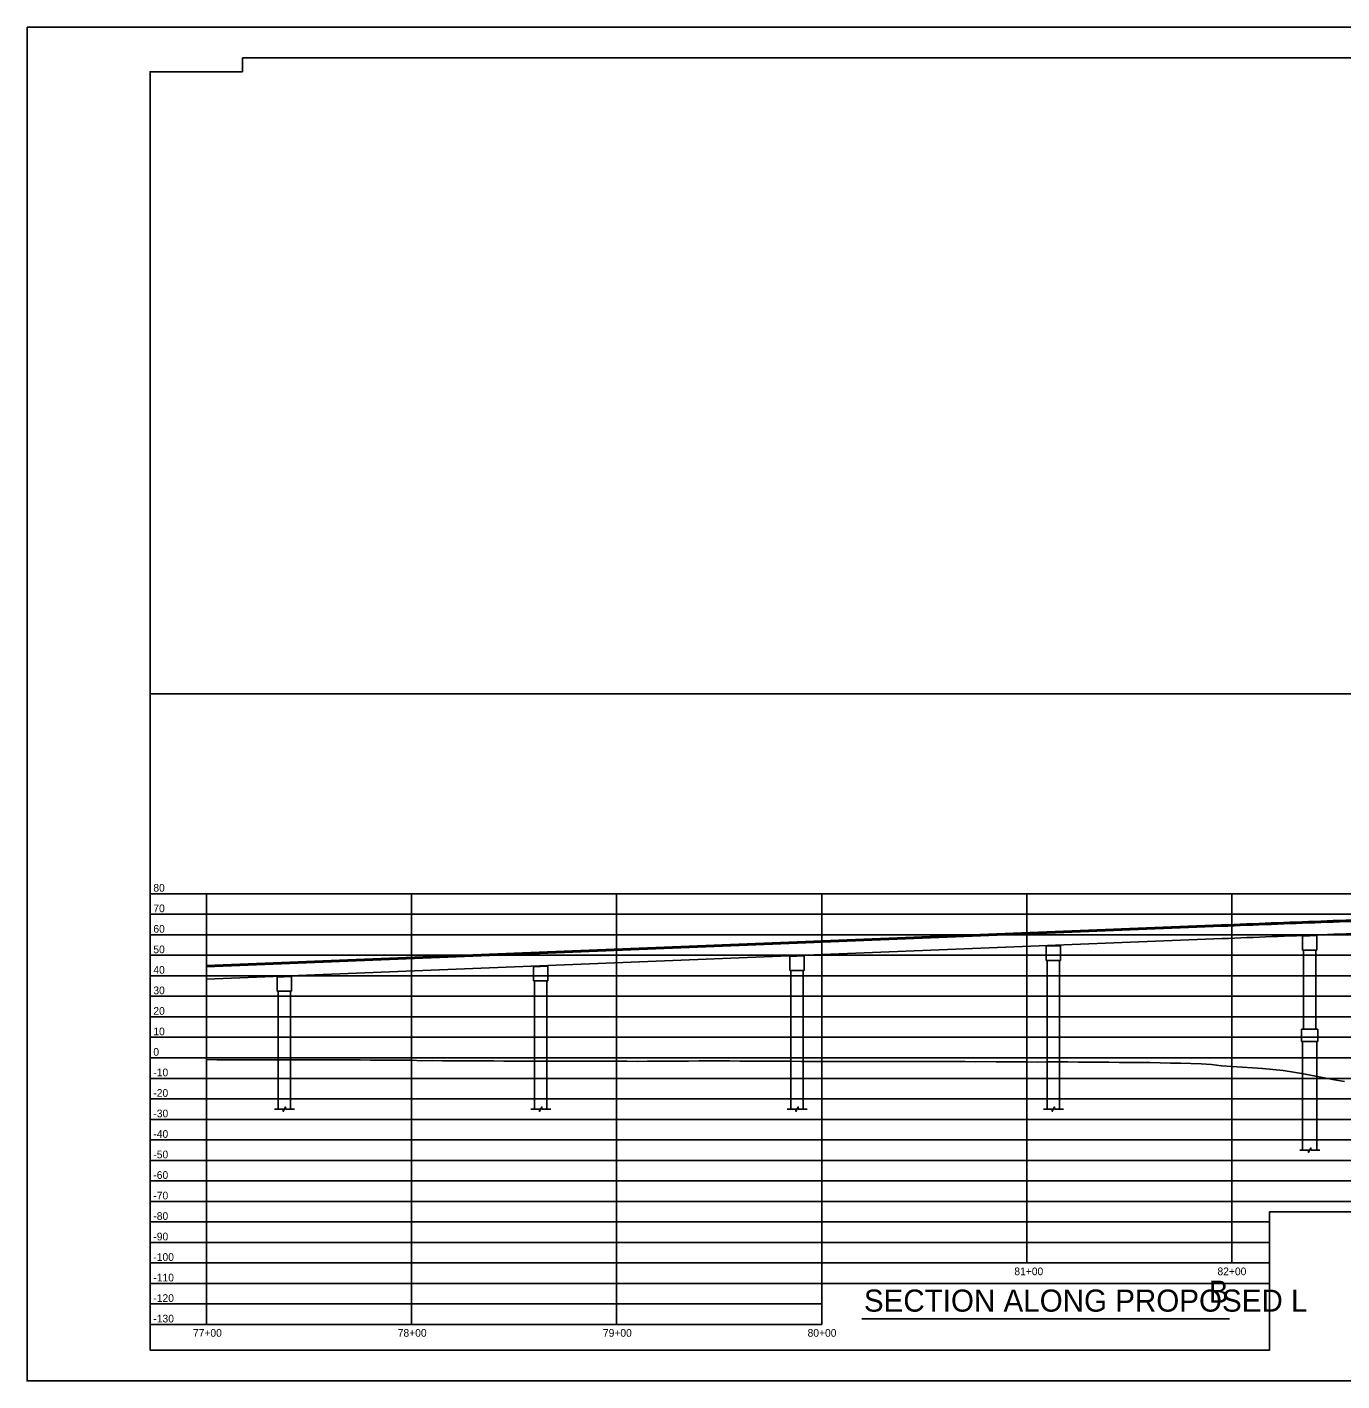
# Model space of a CAD drawing. Extents: x -464 to 4306, y -1372 to 300.
# Drawn here: x 766 to 1407, y -1372 to -712 of the extents above; entities that cross this region are included whole.
import ezdxf

# ---------------------------------------------------------------- set-up
doc = ezdxf.new("R2010")
doc.units = 0
for name, color, linetype in [('BR_AUTO DIMENSION', 7, 'Continuous'), ('BR_BORDER LINES', 7, 'Continuous'), ('BR_GRID LINES', 7, 'Continuous'), ('BR_TEXT', 7, 'Continuous'), ('Mis Ground Lines', 7, 'Continuous'), ('NOPLOT', 7, 'Continuous'), ('Sheet Plot Border Outside CELL', 7, 'Continuous'), ('sub interior bent cap lines', 7, 'Continuous'), ('Sup Concrete Girder Lines', 7, 'Continuous'), ('Sup Concrete Slab Lines', 7, 'Continuous')]:
    doc.layers.add(name, color=color, linetype=linetype)

msp = doc.modelspace()

# ---------------------------------------------------------------- linework, layer by layer
at = {"layer": 'BR_AUTO DIMENSION'}
msp.add_line((853.5, -1164.94), (853.5, -1224.94), dxfattribs=at)
for points in [[(886.62, -1239.94), (890.94, -1239.94), (890.94, -1241.06), (892.06, -1238.83), (892.06, -1239.94), (896.37, -1239.94)], [(1011.62, -1239.94), (1015.94, -1239.94), (1015.94, -1241.06), (1017.06, -1238.83), (1017.06, -1239.94), (1021.37, -1239.94)], [(1136.62, -1239.94), (1140.94, -1239.94), (1140.94, -1241.06), (1142.06, -1238.83), (1142.06, -1239.94), (1146.37, -1239.94)], [(1261.62, -1239.94), (1265.94, -1239.94), (1265.94, -1241.06), (1267.06, -1238.83), (1267.06, -1239.94), (1271.37, -1239.94)], [(1386.62, -1259.94), (1390.94, -1259.94), (1390.94, -1261.06), (1392.06, -1258.83), (1392.06, -1259.94), (1396.37, -1259.94)]]:
    msp.add_lwpolyline(points, dxfattribs=at)
at = {"layer": 'BR_BORDER LINES'}
msp.add_line((826, -1037.44), (1831, -1037.44), dxfattribs=at)
at = {"layer": 'BR_GRID LINES'}
for p, q in [((826, -1134.94), (1831, -1134.94)), ((853.5, -1344.94), (853.5, -1134.94)), ((953.5, -1344.94), (953.5, -1134.94)), ((1053.5, -1344.94), (1053.5, -1134.94)), ((1153.5, -1344.94), (1153.5, -1134.94)), ((1253.5, -1314.94), (1253.5, -1134.94)), ((1353.5, -1314.94), (1353.5, -1134.94)), ((826, -1144.94), (1831, -1144.94)), ((826, -1154.94), (1831, -1154.94)), ((826, -1164.94), (1831, -1164.94)), ((826, -1174.94), (1831, -1174.94)), ((826, -1184.94), (1831, -1184.94)), ((826, -1194.94), (1831, -1194.94)), ((826, -1204.94), (1831, -1204.94)), ((826, -1214.94), (1831, -1214.94)), ((826, -1224.94), (1831, -1224.94)), ((826, -1234.94), (1831, -1234.94)), ((826, -1244.94), (1831, -1244.94)), ((826, -1254.94), (1831, -1254.94)), ((826, -1264.94), (1831, -1264.94)), ((826, -1274.94), (1606, -1274.94)), ((826, -1284.94), (1606, -1284.94)), ((826, -1294.94), (1371.93, -1294.94)), ((826, -1304.94), (1371.93, -1304.94)), ((826, -1314.94), (1371.93, -1314.94)), ((826, -1324.94), (1371.93, -1324.94)), ((826, -1334.94), (1153.5, -1334.94)), ((826, -1344.94), (1153.5, -1344.94))]:
    msp.add_line(p, q, dxfattribs=at)
at = {"layer": 'BR_TEXT'}
msp.add_line((1173.09, -1342.1), (1352.35, -1342.1), dxfattribs=at)
at = {"layer": 'Mis Ground Lines'}
for points in [[(853.5, -1215.83), (858.5, -1215.84), (863.5, -1215.85), (868.5, -1215.86), (873.5, -1215.87), (878.5, -1215.88), (883.5, -1215.89), (888.5, -1215.9), (893.5, -1215.91), (898.5, -1215.92), (903.5, -1215.93), (908.5, -1215.94), (913.5, -1215.95), (918.5, -1215.96), (923.5, -1215.97), (928.5, -1215.98), (933.5, -1216.01), (938.5, -1216.04), (943.5, -1216.07), (948.5, -1216.1), (953.5, -1216.13), (958.5, -1216.34), (963.5, -1216.2), (968.5, -1216.4), (973.5, -1216.41), (978.5, -1216.37), (983.5, -1216.36), (988.5, -1216.42), (993.5, -1216.43), (998.5, -1216.52), (1003.5, -1216.5), (1008.5, -1216.53), (1013.5, -1216.6), (1018.5, -1216.63), (1023.5, -1216.56), (1028.5, -1216.53), (1033.5, -1216.62), (1038.5, -1216.6), (1043.5, -1216.61), (1048.5, -1216.62), (1053.5, -1216.6), (1058.5, -1216.64), (1063.5, -1216.67), (1068.5, -1216.61), (1073.5, -1216.62), (1078.5, -1216.56), (1083.5, -1216.53), (1088.5, -1216.55), (1093.5, -1216.45), (1098.5, -1216.47), (1103.5, -1216.48), (1108.5, -1216.48), (1113.5, -1216.5), (1118.5, -1216.53), (1123.5, -1216.6), (1128.5, -1216.58), (1133.5, -1216.61), (1138.5, -1216.59), (1143.5, -1216.65), (1148.5, -1216.65), (1153.5, -1216.7)], [(1153.5, -1216.7), (1158.5, -1216.75), (1163.5, -1216.71), (1168.5, -1216.77), (1173.5, -1216.7), (1178.5, -1216.74), (1183.5, -1216.75), (1188.5, -1216.67), (1193.5, -1216.75), (1198.5, -1216.7), (1203.5, -1216.78), (1208.5, -1216.8), (1213.5, -1216.8), (1218.5, -1216.8), (1223.5, -1216.78), (1228.5, -1216.81), (1233.5, -1216.77), (1238.5, -1216.84), (1243.5, -1216.85), (1248.5, -1216.85), (1253.5, -1216.96), (1258.5, -1216.99), (1263.5, -1216.91), (1268.5, -1216.92), (1273.5, -1216.86), (1278.5, -1216.98), (1283.5, -1216.99), (1288.5, -1217.02), (1293.5, -1217.11), (1298.5, -1217.14), (1303.5, -1217.25), (1308.5, -1217.14), (1313.5, -1217.24), (1318.5, -1217.33), (1323.5, -1217.48), (1328.5, -1217.58), (1333.5, -1217.76), (1338.5, -1217.94), (1343.5, -1218.14), (1348.5, -1218.79), (1353.5, -1219.12), (1358.5, -1219.48), (1363.5, -1219.83), (1368.5, -1220.21), (1373.5, -1220.56), (1378.5, -1221.19), (1383.5, -1221.99), (1388.5, -1222.79), (1393.5, -1223.68), (1398.5, -1224.64), (1403.5, -1225.59), (1408.5, -1226.47)]]:
    msp.add_lwpolyline(points, dxfattribs=at)
at = {"layer": 'NOPLOT'}
msp.add_lwpolyline([(871, -727.45), (871, -734.19), (826, -734.19), (826, -1357.44), (1371.93, -1357.44), (1371.93, -1289.94), (1606, -1289.94), (1606, -1274.94), (1831, -1274.94), (1831, -747.45), (1756, -747.45), (1756, -727.45)], close=True, dxfattribs=at)
at = {"layer": 'Sheet Plot Border Outside CELL'}
msp.add_lwpolyline([(766, -712.44), (1846, -712.44), (1846, -1372.44), (766, -1372.44)], close=True, dxfattribs=at)
at = {"layer": 'sub interior bent cap lines'}
for p, q in [((1270, -1160.29), (1263, -1160.57)), ((1263, -1160.57), (1263, -1167.43)), ((1270, -1160.29), (1270, -1167.43)), ((1395, -1155.36), (1388, -1155.62)), ((1388, -1155.62), (1388, -1162.49)), ((1395, -1155.36), (1395, -1162.49)), ((1145, -1165.29), (1138, -1165.57)), ((1138, -1165.57), (1138, -1172.43)), ((1145, -1165.29), (1145, -1172.43)), ((1263, -1167.43), (1270, -1167.43)), ((1263.5, -1167.43), (1263.5, -1239.94)), ((1269.5, -1167.43), (1269.5, -1239.94)), ((1388, -1162.49), (1395, -1162.49)), ((1388.5, -1162.49), (1388.5, -1200.94)), ((1394.5, -1162.49), (1394.5, -1200.94)), ((1020, -1170.29), (1013, -1170.57)), ((1013, -1170.57), (1013, -1177.43)), ((1020, -1170.29), (1020, -1177.43)), ((1138, -1172.43), (1145, -1172.43)), ((1138.5, -1172.43), (1138.5, -1239.94)), ((1144.5, -1172.43), (1144.5, -1239.94)), ((895, -1175.29), (888, -1175.57)), ((888, -1175.57), (888, -1182.43)), ((895, -1175.29), (895, -1182.43)), ((1013, -1177.43), (1020, -1177.43)), ((1013.5, -1177.43), (1013.5, -1239.94)), ((1019.5, -1177.43), (1019.5, -1239.94)), ((888, -1182.43), (895, -1182.43)), ((888.5, -1182.43), (888.5, -1239.94)), ((894.5, -1182.43), (894.5, -1239.94)), ((1387.5, -1200.94), (1395.5, -1200.94)), ((1387.5, -1200.94), (1387.5, -1206.94)), ((1395.5, -1200.94), (1395.5, -1206.94)), ((1387.5, -1206.94), (1395.5, -1206.94)), ((1388, -1206.94), (1388, -1259.94)), ((1395, -1206.94), (1395, -1259.94))]:
    msp.add_line(p, q, dxfattribs=at)
at = {"layer": 'Sup Concrete Girder Lines'}
for p, q in [((853.5, -1170.61), (1348.53, -1150.81)), ((853.5, -1176.62), (1348.77, -1156.81))]:
    msp.add_line(p, q, dxfattribs=at)
for points in [[(1348.53, -1150.81), (1372.73, -1149.86), (1396.92, -1148.95), (1421.12, -1148.08), (1445.32, -1147.25), (1469.52, -1146.45), (1493.72, -1145.7), (1517.92, -1144.98), (1542.12, -1144.31), (1566.32, -1143.67), (1590.52, -1143.07), (1614.71, -1142.51), (1638.91, -1141.98), (1663.11, -1141.5), (1687.31, -1141.05), (1711.51, -1140.65), (1735.71, -1140.28), (1759.91, -1139.95), (1784.11, -1139.66), (1803.54, -1139.45)], [(1348.76, -1156.81), (1372.96, -1155.86), (1397.15, -1154.95), (1421.33, -1154.08), (1445.52, -1153.25), (1469.71, -1152.45), (1493.9, -1151.7), (1518.09, -1150.98), (1542.28, -1150.3), (1566.47, -1149.67), (1590.66, -1149.07), (1614.85, -1148.5), (1639.04, -1147.98), (1663.23, -1147.5), (1687.42, -1147.05), (1711.61, -1146.65), (1735.8, -1146.28), (1759.99, -1145.95), (1784.17, -1145.66), (1803.54, -1145.45)]]:
    msp.add_spline(points, degree=3, dxfattribs=at)
at = {"layer": 'Sup Concrete Slab Lines'}
msp.add_line((853.5, -1169.94), (1348.5, -1150.14), dxfattribs=at)
msp.add_spline([(1348.5, -1150.14), (1372.7, -1149.2), (1396.9, -1148.29), (1421.1, -1147.41), (1445.3, -1146.58), (1469.5, -1145.79), (1493.7, -1145.03), (1517.9, -1144.32), (1542.1, -1143.64), (1566.3, -1143), (1590.5, -1142.4), (1614.7, -1141.84), (1638.9, -1141.32), (1663.1, -1140.83), (1687.3, -1140.39), (1711.5, -1139.98), (1735.7, -1139.61), (1759.9, -1139.28), (1784.1, -1138.99), (1803.54, -1138.79)], degree=3, dxfattribs=at)

# ---------------------------------------------------------------- texts
at = {"layer": 'BR_TEXT'}
for s, p in [('80', (827.58, -1133.94)), ('70', (827.58, -1143.94)), ('60', (827.58, -1153.94)), ('50', (827.58, -1163.94)), ('40', (827.58, -1173.94)), ('30', (827.58, -1183.94)), ('20', (827.58, -1193.94)), ('10', (827.58, -1203.94)), ('0', (827.58, -1213.94)), ('-10', (827.58, -1223.94)), ('-20', (827.58, -1233.94)), ('-30', (827.58, -1243.94)), ('-40', (827.58, -1253.94)), ('-50', (827.58, -1263.94)), ('-60', (827.58, -1273.94)), ('-70', (827.58, -1283.94)), ('-80', (827.58, -1293.94)), ('-90', (827.58, -1303.94)), ('-100', (827.58, -1313.94)), ('81+00', (1247.43, -1320.91)), ('82+00', (1346.49, -1320.91)), ('-110', (827.58, -1323.94)), ('-120', (827.58, -1333.94)), ('-130', (827.58, -1343.94)), ('77+00', (846.9, -1350.91)), ('78+00', (946.75, -1350.91)), ('79+00', (1046.81, -1350.91)), ('80+00', (1146.61, -1350.91))]:
    msp.add_text(s, height=3.75, rotation=360, dxfattribs=at).set_placement(p)
for s, height, p in [('B', 10.78, (1342.24, -1334.33)), ('SECTION ALONG PROPOSED L', 10.7809, (1174.07, -1338.69))]:
    msp.add_text(s, height=height, dxfattribs=at).set_placement(p)

doc.saveas('drawing.dxf')
